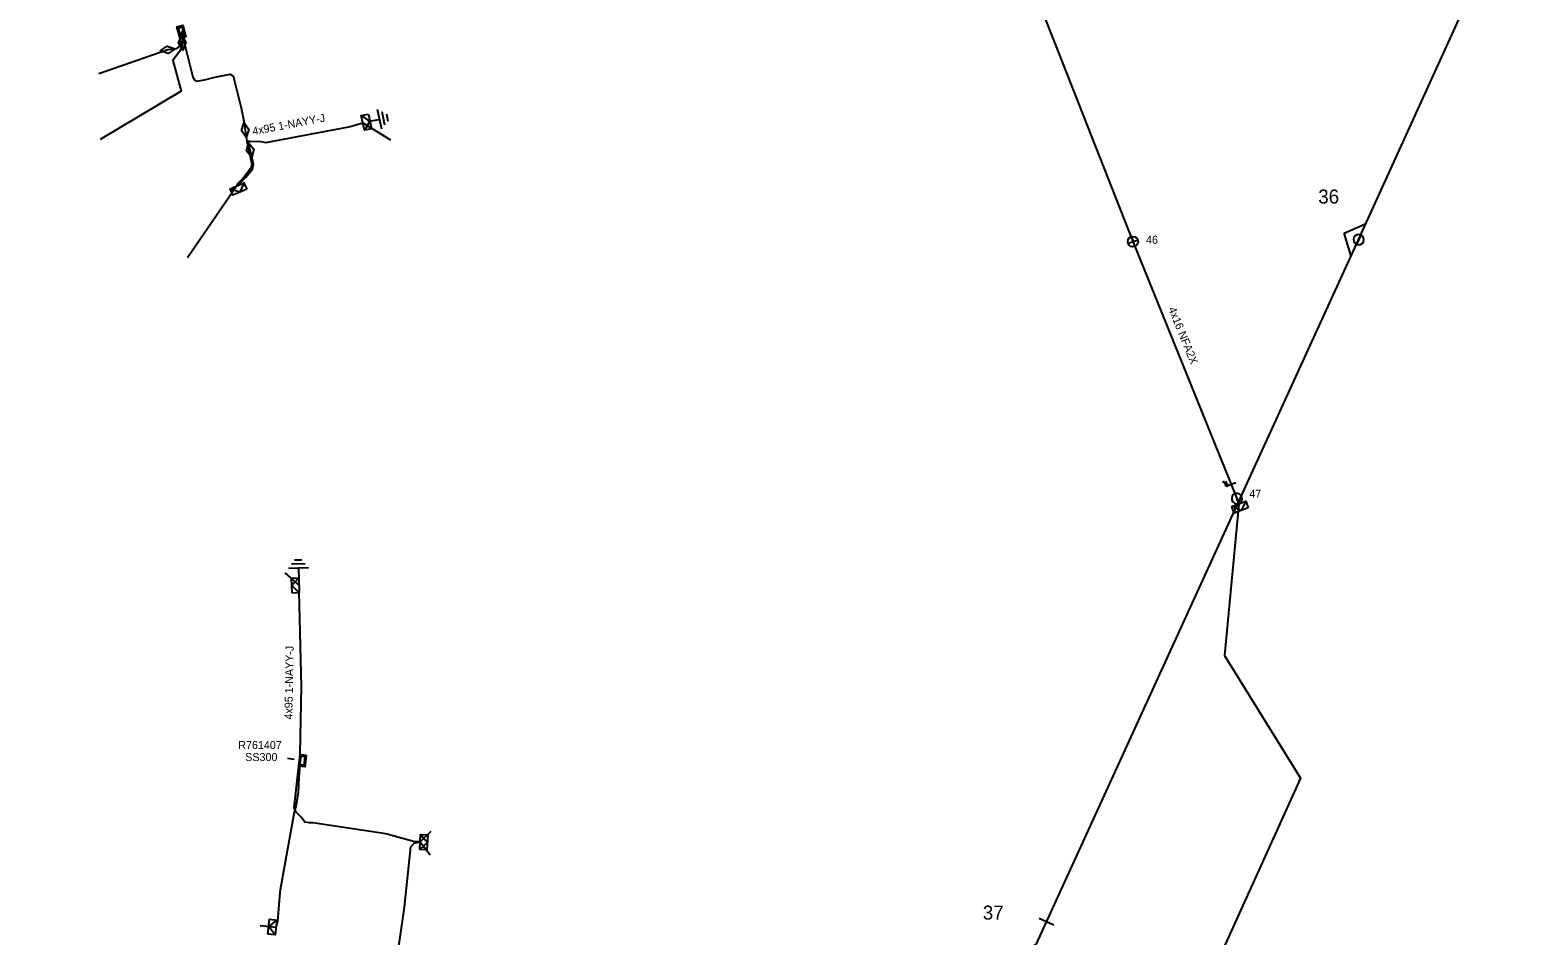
# Model space of a CAD drawing. Extents: x -540028 to -538776, y -1157064 to -1155670.
# Drawn here: x -539627.5 to -539441, y -1156700.4 to -1156587.3 of the extents above; entities that cross this region are included whole.
import ezdxf

# ---------------------------------------------------------------- set-up
doc = ezdxf.new("R2010")
doc.units = 0
for name, color, linetype in [('Implicitní', 7, 'Continuous'), ('Vrstva 13', 7, 'Continuous'), ('Vrstva 14', 7, 'Continuous'), ('Vrstva 15', 7, 'Continuous'), ('Vrstva 18', 7, 'Continuous'), ('Vrstva 19', 7, 'Continuous'), ('Vrstva 2', 7, 'Continuous'), ('Vrstva 28', 7, 'Continuous'), ('Vrstva 29', 7, 'Continuous'), ('Vrstva 30', 7, 'Continuous'), ('Vrstva 31', 7, 'Continuous'), ('Vrstva 5', 7, 'Continuous'), ('Vrstva 50', 7, 'Continuous'), ('Vrstva 51', 7, 'Continuous'), ('Vrstva 52', 7, 'Continuous'), ('Vrstva 54', 7, 'Continuous'), ('Vrstva 59', 7, 'Continuous'), ('Vrstva 6', 7, 'Continuous')]:
    doc.layers.add(name, color=color, linetype=linetype)

# ---------------------------------------------------------------- blocks, each defined once
blk = doc.blocks.new('326')
at = {"layer": 'Vrstva 2'}
blk.add_line((0, 2), (0, -2), dxfattribs=at)
blk = doc.blocks.new('16')
at = {"layer": 'Vrstva 2'}
for p, q in [((-4.5, 0), (0, 4)), ((0, 4), (4.5, 0))]:
    blk.add_line(p, q, dxfattribs=at)
blk = doc.blocks.new('5')
at = {"layer": 'Implicitní'}
blk.add_line((1.3, 0), (-1.3, 0), dxfattribs=at)
blk.add_arc((0, 0), 1.3, 180, 0, dxfattribs=at)
at = {"layer": 'Vrstva 2'}
blk.add_arc((0, 0), 1.3, 0, 180, dxfattribs=at)
blk = doc.blocks.new('NN840')
at = {"layer": 'Vrstva 15'}
for points in [[(0, 0.62), (0, -0.63)], [(-0.75, -0.71), (-0.75, -0.66)], [(-0.73, -0.76), (-0.75, -0.71)], [(-0.66, -0.8), (-0.73, -0.76)], [(-0.63, -0.8), (-0.66, -0.8)], [(-0.56, -0.76), (-0.63, -0.8)], [(-0.54, -0.71), (-0.56, -0.76)], [(-0.54, -0.38), (-0.54, -0.71)], [(-0.33, -0.38), (-0.33, -0.8)], [(-0.33, -0.64), (-0.13, -0.38)], [(-0.26, -0.56), (-0.09, -0.8)]]:
    blk.add_lwpolyline(points, dxfattribs=at)
blk = doc.blocks.new('17')
at = {"layer": 'Vrstva 2'}
blk.add_lwpolyline([(-1.875, 0), (0, 0.9375), (1.875, 0), (0, -0.9375)], close=True, dxfattribs=at)
blk = doc.blocks.new('132')
at = {"layer": 'Vrstva 2'}
for points in [[(-1.5, 1.5), (1.5, 1.5), (1.5, 0), (-1.5, 0)], [(-1.1, 1.2), (1.1, 1.2), (1.1, 0.3), (-1.1, 0.3)]]:
    blk.add_lwpolyline(points, close=True, dxfattribs=at)
blk = doc.blocks.new('23')
at = {"layer": 'Vrstva 2'}
blk.add_lwpolyline([(1.875, -1.8), (-1.875, -1.8), (-1.875, 0), (1.875, 0)], close=True, dxfattribs=at)
blk.add_lwpolyline([(1.875, 0), (0, -1.8), (-1.875, 0)], dxfattribs=at)
blk = doc.blocks.new('11')
at = {"layer": 'Vrstva 2'}
for p, q in [((0, -4.3), (0, -1.3)), ((-2.5, -4.3), (2.5, -4.3)), ((-1.7, -5.3), (1.7, -5.3)), ((-0.9, -6.3), (0.9, -6.3))]:
    blk.add_line(p, q, dxfattribs=at)
blk = doc.blocks.new('1')
at = {"layer": 'Vrstva 2'}
for p, q in [((-1.3, 0), (1.3, 0)), ((0, -1.3), (0, 1.3))]:
    blk.add_line(p, q, dxfattribs=at)
blk.add_circle((0, 0), 1.3, dxfattribs=at)

msp = doc.modelspace()

# ---------------------------------------------------------------- linework, layer by layer
at = {"layer": 'Vrstva 5'}
for points in [[(-539608.19, -1156587.32), (-539608.39, -1156587.38), (-539608.74, -1156588.06), (-539608.7, -1156589.25), (-539609.19, -1156589.64), (-539610.25, -1156589.78)], [(-539608.14, -1156587.52), (-539608.33, -1156587.57), (-539608.49, -1156587.97), (-539608.43, -1156588.88)], [(-539608.09, -1156587.71), (-539608.18, -1156587.74), (-539608.36, -1156588.18), (-539607.1, -1156593.18), (-539606.88, -1156593.53), (-539606.62, -1156593.69), (-539605.66, -1156593.52), (-539604.34, -1156593.19), (-539602.43, -1156592.82), (-539602.05, -1156593.04), (-539601.09, -1156597.01), (-539600.75, -1156598.67), (-539600.58, -1156599.8)], [(-539599.94, -1156602.3), (-539600.18, -1156601.15), (-539599.93, -1156601.23), (-539598.88, -1156601.18), (-539597.97, -1156601.34), (-539587.61, -1156599.38), (-539585.87, -1156598.91)], [(-539600.58, -1156599.8), (-539600.37, -1156601.19), (-539600.13, -1156602.34), (-539599.73, -1156604.06), (-539599.86, -1156604.58), (-539600.66, -1156605.6), (-539601.21, -1156606.17), (-539601.56, -1156606.56), (-539601.6, -1156606.75), (-539601.41, -1156606.69), (-539601.06, -1156606.31), (-539600.51, -1156605.73), (-539599.67, -1156604.67), (-539599.52, -1156604.06), (-539599.94, -1156602.3)], [(-539593.76, -1156678.46), (-539593.7, -1156678.38), (-539593.65, -1156678.17), (-539593.71, -1156677.74), (-539593.55, -1156669.29), (-539593.61, -1156666.05), (-539593.75, -1156660.85), (-539593.82, -1156657.55), (-539593.79, -1156656.98), (-539593.84, -1156656.69)], [(-539581.84, -1156705.01), (-539580.66, -1156696.9), (-539579.86, -1156689.38), (-539579.46, -1156688.91), (-539578.71, -1156688.76), (-539579.55, -1156688.7), (-539582.98, -1156687.74), (-539592.11, -1156686.36), (-539592.53, -1156686.37), (-539593.13, -1156686.27), (-539593.54, -1156685.7), (-539594.14, -1156685.1), (-539594.45, -1156684.51), (-539593.85, -1156679.23), (-539593.73, -1156678.8), (-539593.79, -1156678.69)]]:
    msp.add_lwpolyline(points, dxfattribs=at)
at = {"layer": 'Vrstva 50'}
msp.add_lwpolyline([(-539501.61, -1156583.33), (-539489.66, -1156613.73), (-539476.68, -1156645.85)], dxfattribs=at)
at = {"layer": 'Vrstva 52'}
for points in [[(-539657.4, -1156814), (-539621.96, -1156789.44), (-539562.03, -1156745.14), (-539501.72, -1156701.5), (-539461.47, -1156613.51), (-539433.27, -1156551.44), (-539397.51, -1156471.99), (-539336.12, -1156442.56)], [(-539608.43, -1156588.88), (-539608.45, -1156589.29), (-539608.78, -1156589.96), (-539609.61, -1156591.11), (-539608.55, -1156594.95), (-539618.68, -1156600.98)], [(-539610.25, -1156589.78), (-539618.85, -1156592.77)], [(-539593.77, -1156678.56), (-539593.68, -1156678.73), (-539593.74, -1156679.15), (-539593.88, -1156680.72), (-539593.97, -1156682.49), (-539594.21, -1156684.11), (-539594.46, -1156685.03), (-539596.21, -1156694.74), (-539596.24, -1156695.09), (-539596.53, -1156698.68), (-539596.72, -1156699.45)]]:
    msp.add_lwpolyline(points, dxfattribs=at)
at = {"layer": 'Vrstva 54'}
msp.add_lwpolyline([(-539476.68, -1156645.85), (-539476.45, -1156646.5)], dxfattribs=at)
at = {"layer": 'Vrstva 59'}
for points in [[(-539585.87, -1156598.91), (-539582.4, -1156601)], [(-539601.6, -1156606.75), (-539607.76, -1156615.78)], [(-539476.45, -1156646.5), (-539478.22, -1156665.48), (-539468.73, -1156680.79), (-539490.57, -1156728.99), (-539524.92, -1156802.24), (-539547.6, -1156852.94), (-539581.45, -1156837.99)], [(-539593.84, -1156656.69), (-539595.59, -1156655.11)], [(-539594.44, -1156678.45), (-539595.28, -1156678.34)], [(-539578.71, -1156688.76), (-539577.34, -1156687.4)], [(-539578.71, -1156688.76), (-539577.45, -1156690.37)], [(-539596.72, -1156699.45), (-539598.69, -1156699.24)]]:
    msp.add_lwpolyline(points, dxfattribs=at)

# ---------------------------------------------------------------- block references
at = {"layer": 'Vrstva 13'}
for name, p, xscale, yscale, rotation in [('1', (-539489.66, -1156613.73), 0.5, 0.5, -73.05349442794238), ('5', (-539461.47, -1156613.51), 0.49999999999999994, 0.5000000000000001, 65.41888612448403), ('5', (-539476.68, -1156645.85), 0.5, 0.5, -73.05349442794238)]:
    msp.add_blockref(name, p, dxfattribs=dict(at, xscale=xscale, yscale=yscale, rotation=rotation))
at = {"layer": 'Vrstva 15', "xscale": 0.5, "yscale": 0.5}
for p, rotation in [((-539585.87, -1156598.91), 101.768286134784), ((-539593.84, -1156656.69), -178.21008948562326)]:
    msp.add_blockref('11', p, dxfattribs=dict(at, rotation=rotation))
at = {"layer": 'Vrstva 18', "xscale": 0.5, "yscale": 0.5}
for name, p, rotation in [('16', (-539461.47, -1156613.51), 65.41884168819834), ('326', (-539500.46, -1156698.74), -114.5811721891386)]:
    msp.add_blockref(name, p, dxfattribs=dict(at, rotation=rotation))
at = {"layer": 'Vrstva 18', "rotation": -69.1363577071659}
msp.add_blockref('NN840', (-539477.38, -1156644.12), dxfattribs=at)
at = {"layer": 'Vrstva 19', "xscale": 0.5}
for p, yscale, rotation in [((-539610.25, -1156589.78), 0.5000000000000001, 7.523819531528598), ((-539608.43, -1156588.88), 0.5000000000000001, -86.02225835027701), ((-539600.58, -1156599.8), 0.5, -81.72956440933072), ((-539599.94, -1156602.3), 0.5, -76.74112780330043)]:
    msp.add_blockref('17', p, dxfattribs=dict(at, yscale=yscale, rotation=rotation))
at = {"layer": 'Vrstva 28'}
for p, xscale, yscale, rotation in [((-539608.17, -1156587.42), 0.49999999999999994, 0.5000000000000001, 104.81603888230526), ((-539593.77, -1156678.56), 0.5000000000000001, 0.5, -96.58194466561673)]:
    msp.add_blockref('132', p, dxfattribs=dict(at, xscale=xscale, yscale=yscale, rotation=rotation))
at = {"layer": 'Vrstva 31'}
for p, xscale, yscale, rotation in [((-539585.87, -1156598.91), 0.5, 0.5, 101.768286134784), ((-539601.6, -1156606.75), 0.49999999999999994, 0.5000000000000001, 23.536620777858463), ((-539476.45, -1156646.5), 0.5000000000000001, 0.5, 20.70299439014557), ((-539593.84, -1156656.69), 0.49999999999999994, 0.4999999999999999, -88.21008934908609), ((-539578.71, -1156688.76), 0.5, 0.5, 86.30861396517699), ((-539596.72, -1156699.45), 0.49999999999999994, 0.4999999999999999, -96.3401917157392)]:
    msp.add_blockref('23', p, dxfattribs=dict(at, xscale=xscale, yscale=yscale, rotation=rotation))

# ---------------------------------------------------------------- texts
at = {"layer": 'Vrstva 14'}
for s, p in [('36', (-539466.51, -1156608.98)), ('37', (-539508.42, -1156698.47))]:
    msp.add_text(s, height=1.75, dxfattribs=at).set_placement(p)
for s, rotation, p in [('46', 359.987, (-539488.03, -1156614.01)), ('47', 0.019, (-539475.13, -1156645.75))]:
    msp.add_text(s, height=1, rotation=rotation, dxfattribs=at).set_placement(p)
at = {"layer": 'Vrstva 29'}
msp.add_text('R761407', height=1, dxfattribs=at).set_placement((-539601.43, -1156677.15))
at = {"layer": 'Vrstva 30'}
msp.add_text('SS300', height=1, dxfattribs=at).set_placement((-539600.56, -1156678.65))
at = {"layer": 'Vrstva 51'}
msp.add_text('4x16 NFA2X', height=1, rotation=292.005, dxfattribs=at).set_placement((-539485.27, -1156622.14))
at = {"layer": 'Vrstva 6'}
for rotation, p in [(10.713, (-539599.57, -1156600.44)), (88.915, (-539594.68, -1156673.47))]:
    msp.add_text('4x95 1-NAYY-J', height=1, rotation=rotation, dxfattribs=at).set_placement(p)

doc.saveas('drawing.dxf')
